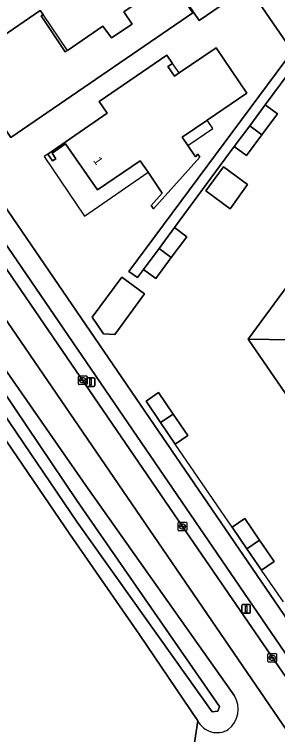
# Model space of a CAD drawing. Extents: x 155275 to 156265, y 382654 to 383635.
# Drawn here: x 155707.5 to 155738, y 383185 to 383268.4 of the extents above; entities that cross this region are included whole.
import ezdxf

# ---------------------------------------------------------------- set-up
doc = ezdxf.new("R2010")
doc.units = 0
for name, color, linetype in [('IMGEO_Erf', 7, 'Continuous'), ('IMGEO_Groenvoorziening', 7, 'Continuous'), ('IMGEO_Haag', 7, 'Continuous'), ('IMGEO_Hek', 7, 'Continuous'), ('IMGEO_Kolk', 7, 'Continuous'), ('IMGEO_Lichtmast', 7, 'Continuous'), ('IMGEO_Loofbos', 7, 'Continuous'), ('IMGEO_Oever', 7, 'Continuous'), ('IMGEO_Pand', 7, 'Continuous'), ('IMGEO_Pand_nummerreeks', 7, 'Continuous'), ('IMGEO_Pand_overbouw', 7, 'Continuous'), ('IMGEO_Rijbaan_lokaal_gesloten', 7, 'Continuous'), ('IMGEO_Voetpad_open', 7, 'Continuous'), ('IMGEO_Waterloop', 7, 'Continuous')]:
    doc.layers.add(name, color=color, linetype=linetype)

msp = doc.modelspace()

# ---------------------------------------------------------------- linework, layer by layer
at = {"layer": 'IMGEO_Erf'}
for points in [[(155693.884, 383330.96), (155734.469, 383271.59), (155728.87, 383267.725), (155692.93, 383320.467), (155688.369, 383327.082)], [(155685.56, 383327.69), (155661.788, 383311.41), (155661.818, 383311.37), (155722.08, 383223.219), (155746.422, 383187.612), (155746.888, 383186.944), (155747.971, 383187.224)], [(155745.485, 383270.128), (155742.752, 383266.412), (155744.176, 383265.359), (155742.385, 383262.935), (155740.594, 383260.512), (155739.169, 383261.565), (155736.524, 383257.973), (155737.942, 383256.92), (155736.147, 383254.502), (155734.353, 383252.085), (155732.935, 383253.137), (155726.011, 383243.752), (155727.435, 383242.698), (155725.643, 383240.277), (155723.851, 383237.856), (155722.428, 383238.91), (155721.741, 383237.982), (155720.716, 383238.675), (155753.838, 383283.279)], [(155739.704, 383223.29), (155734.527, 383230.848), (155740.14, 383238.453)]]:
    msp.add_lwpolyline(points, dxfattribs=at)
for points in [[(155734.583, 383271.594), (155742.867, 383277.178), (155744.174, 383279.002), (155741.521, 383282.885), (155742.428, 383283.521), (155739.813, 383287.344), (155749.57, 383293.989), (155754.229, 383287.144), (155752.824, 383286.188), (155752.675, 383286.086), (155752.585, 383286.218), (155751.334, 383285.368), (155751.99, 383284.392), (155753.037, 383282.834), (155739.444, 383264.478)], [(155728.147, 383268.629), (155707.057, 383254.188), (155704.717, 383257.623), (155705.227, 383257.972), (155704.294, 383259.337), (155704.145, 383259.236), (155701.658, 383262.871), (155710.458, 383268.888), (155710.791, 383268.434), (155710.55, 383268.256), (155713.354, 383264.091), (155713.617, 383264.267), (155717.71, 383267.089), (155718.705, 383265.728), (155721.105, 383267.326), (155720.14, 383268.738), (155725.534, 383272.422)], [(155734.407, 383259.334), (155729.803, 383256.198), (155729.751, 383256.162), (155726.905, 383254.223), (155727.564, 383253.254), (155728.445, 383251.962), (155728.711, 383252.244), (155728.949, 383251.893), (155723.566, 383245.941), (155723.308, 383246.322), (155724.598, 383247.753), (155722.951, 383250.17), (155722.046, 383251.498), (155717.08, 383248.118), (155713.404, 383253.462), (155711.832, 383252.387), (155712.272, 383251.719), (155711.884, 383251.464), (155711.333, 383252.262), (155718.216, 383257.009), (155717.282, 383258.364), (155725.125, 383263.723), (155725.785, 383262.769), (155725.246, 383262.397), (155726.007, 383261.296), (155726.548, 383261.665), (155730.828, 383264.587)], [(155734.487, 383248.749), (155732.466, 383245.916), (155729.635, 383248.005), (155731.701, 383250.805)], [(155722.555, 383236.09), (155719.101, 383231.389), (155717.78, 383231.439), (155716.477, 383233.378), (155719.909, 383238)], [(155727.572, 383219.678), (155726.107, 383218.678), (155724.41, 383221.165), (155722.713, 383223.652), (155724.178, 383224.652), (155725.875, 383222.165)], [(155737.567, 383205.079), (155736.107, 383204.078), (155734.403, 383206.563), (155732.698, 383209.047), (155734.158, 383210.049), (155735.862, 383207.564)]]:
    msp.add_lwpolyline(points, close=True, dxfattribs=at)
at = {"layer": 'IMGEO_Groenvoorziening'}
for points in [[(155724.288, 383171.628), (155724.536, 383171.272), (155727.184, 383173.115), (155741.62, 383181.726), (155659.414, 383301.908), (155653.216, 383310.97)], [(155661.264, 383305.321), (155662.23, 383303.795), (155718.824, 383220.994), (155726.923, 383209.144), (155742.91, 383185.882), (155743.508, 383186.026), (155744.463, 383186.256), (155720.116, 383221.876), (155661.229, 383308.029)], [(155652.603, 383306.481), (155666.3, 383286.64), (155695.288, 383243.3), (155715.747, 383213.896), (155732.948, 383189.534)], [(155728.723, 383186.646), (155727.137, 383176.194), (155722.162, 383175.473), (155711.113, 383178.69), (155713.945, 383176.906), (155717.284, 383175.138), (155722.257, 383173.065)]]:
    msp.add_lwpolyline(points, dxfattribs=at)
for centre, radius, start, end in [((155730.411, 383187.98), 2.975, 308.07903, 31.49251), ((155730.943, 383187.744), 2.477, 206.32515, 301.7411)]:
    msp.add_arc(centre, radius, start, end, dxfattribs=at)
at = {"layer": 'IMGEO_Haag'}
msp.add_lwpolyline([(155661.264, 383305.321), (155662.23, 383303.795), (155718.824, 383220.994), (155726.923, 383209.144), (155742.91, 383185.882), (155743.508, 383186.026), (155744.463, 383186.256), (155720.116, 383221.876), (155661.229, 383308.029)], dxfattribs=at)
at = {"layer": 'IMGEO_Hek'}
for points in [[(155732.698, 383209.047), (155726.107, 383218.678)], [(155738.647, 383200.418), (155736.107, 383204.078)]]:
    msp.add_lwpolyline(points, dxfattribs=at)
at = {"layer": 'IMGEO_Kolk'}
for p, q in [((155714.878, 383225.653), (155714.878, 383226.505)), ((155714.953, 383226.579), (155715.805, 383226.579)), ((155715.879, 383226.505), (155715.879, 383225.653)), ((155715.805, 383225.579), (155714.953, 383225.579)), ((155715.137, 383226.073), (155715.137, 383226.085)), ((155715.575, 383226.036), (155715.177, 383226.036)), ((155715.18, 383226.122), (155715.578, 383226.122)), ((155715.389, 383225.799), (155715.364, 383225.799)), ((155715.366, 383226.359), (155715.391, 383226.359)), ((155715.621, 383226.085), (155715.621, 383226.073)), ((155726.422, 383208.718), (155726.422, 383209.57)), ((155726.497, 383209.644), (155727.349, 383209.644)), ((155726.681, 383209.138), (155726.681, 383209.15)), ((155727.119, 383209.101), (155726.721, 383209.101)), ((155726.724, 383209.187), (155727.122, 383209.187)), ((155726.933, 383208.864), (155726.908, 383208.864)), ((155726.91, 383209.424), (155726.935, 383209.424)), ((155727.165, 383209.15), (155727.165, 383209.138)), ((155727.423, 383209.57), (155727.423, 383208.718)), ((155727.349, 383208.644), (155726.497, 383208.644)), ((155736.832, 383193.505), (155736.832, 383194.357)), ((155736.907, 383194.431), (155737.759, 383194.431)), ((155737.091, 383193.925), (155737.091, 383193.937)), ((155737.529, 383193.888), (155737.131, 383193.888)), ((155737.134, 383193.974), (155737.532, 383193.974)), ((155737.32, 383194.211), (155737.345, 383194.211)), ((155737.575, 383193.937), (155737.575, 383193.925)), ((155737.833, 383194.357), (155737.833, 383193.505)), ((155737.759, 383193.431), (155736.907, 383193.431)), ((155737.343, 383193.651), (155737.318, 383193.651))]:
    msp.add_line(p, q, dxfattribs=at)
for points in [[(155714.878, 383225.653), (155714.878, 383226.505)], [(155714.953, 383226.579), (155715.805, 383226.579)], [(155715.879, 383226.505), (155715.879, 383225.653)], [(155715.805, 383225.579), (155714.953, 383225.579)], [(155726.422, 383208.718), (155726.422, 383209.57)], [(155726.497, 383209.644), (155727.349, 383209.644)], [(155727.423, 383209.57), (155727.423, 383208.718)], [(155727.349, 383208.644), (155726.497, 383208.644)], [(155736.832, 383193.505), (155736.832, 383194.357)], [(155736.907, 383194.431), (155737.759, 383194.431)], [(155737.833, 383194.357), (155737.833, 383193.505)], [(155737.759, 383193.431), (155736.907, 383193.431)]]:
    msp.add_lwpolyline(points, dxfattribs=at)
for centre, radius, start, end in [((155714.955, 383226.503), 0.0765, 91.55205, 178.44795), ((155714.955, 383226.503), 0.0765, 91.55205, 178.44795), ((155715.803, 383226.503), 0.0765, 1.55205, 88.44795), ((155715.803, 383226.503), 0.0765, 1.55205, 88.44795), ((155714.955, 383225.655), 0.0765, 181.55205, 268.44795), ((155714.955, 383225.655), 0.0765, 181.55205, 268.44795), ((155715.177, 383226.082), 0.0403, 85.87752, 175.75265), ((155715.174, 383226.072), 0.0366, 178.93798, 274.71019), ((155715.578, 383226.079), 0.043, 264.86636, 352.45326), ((155715.582, 383226.084), 0.0386, 1.73085, 96.63898), ((155715.803, 383225.655), 0.0765, 271.55205, 358.44795), ((155715.803, 383225.655), 0.0765, 271.55205, 358.44795), ((155726.499, 383209.568), 0.0765, 91.55205, 178.44795), ((155726.499, 383209.568), 0.0765, 91.55205, 178.44795), ((155726.721, 383209.147), 0.0403, 85.87752, 175.75265), ((155726.718, 383209.137), 0.0366, 178.93798, 274.71019), ((155727.122, 383209.144), 0.043, 264.86636, 352.45326), ((155727.126, 383209.149), 0.0386, 1.73085, 96.63898), ((155727.347, 383209.568), 0.0765, 1.55205, 88.44795), ((155727.347, 383209.568), 0.0765, 1.55205, 88.44795), ((155726.499, 383208.72), 0.0765, 181.55205, 268.44795), ((155726.499, 383208.72), 0.0765, 181.55205, 268.44795), ((155727.347, 383208.72), 0.0765, 271.55205, 358.44795), ((155727.347, 383208.72), 0.0765, 271.55205, 358.44795), ((155736.909, 383194.355), 0.0765, 91.55205, 178.44795), ((155736.909, 383194.355), 0.0765, 91.55205, 178.44795), ((155737.131, 383193.934), 0.0403, 85.87752, 175.75265), ((155737.128, 383193.924), 0.0366, 178.93798, 274.71019), ((155737.532, 383193.931), 0.043, 264.86636, 352.45326), ((155737.536, 383193.936), 0.0386, 1.73085, 96.63898), ((155737.757, 383194.355), 0.0765, 1.55205, 88.44795), ((155737.757, 383194.355), 0.0765, 1.55205, 88.44795), ((155736.909, 383193.507), 0.0765, 181.55205, 268.44795), ((155736.909, 383193.507), 0.0765, 181.55205, 268.44795), ((155737.757, 383193.507), 0.0765, 271.55205, 358.44795), ((155737.757, 383193.507), 0.0765, 271.55205, 358.44795)]:
    msp.add_arc(centre, radius, start, end, dxfattribs=at)
for centre, major_axis, ratio, start_param, end_param in [((155715.365, 383226.079), (-0.387, 0.002), 0.722429, 4.712389, 7.853982), ((155715.39, 383226.079), (-0.39, 0.002), 0.717154, 1.570796, 4.712389), ((155726.909, 383209.144), (-0.387, 0.002), 0.722429, 4.712389, 7.853982), ((155726.934, 383209.144), (-0.39, 0.002), 0.717154, 1.570796, 4.712389), ((155737.319, 383193.931), (-0.387, 0.002), 0.722429, 4.712389, 7.853982), ((155737.344, 383193.931), (-0.39, 0.002), 0.717154, 1.570796, 4.712389)]:
    msp.add_ellipse(centre, major_axis=major_axis, ratio=ratio, start_param=start_param, end_param=end_param, dxfattribs=at)
at = {"layer": 'IMGEO_Lichtmast'}
for p, q in [((155715.784, 383225.465), (155715.784, 383226.265)), ((155715.784, 383226.265), (155715.784, 383225.465)), ((155715.884, 383226.365), (155716.674, 383226.365)), ((155716.674, 383226.365), (155715.884, 383226.365)), ((155716.774, 383226.265), (155716.774, 383225.465)), ((155716.774, 383225.465), (155716.774, 383226.265)), ((155716.674, 383225.365), (155715.884, 383225.365)), ((155715.884, 383225.365), (155716.674, 383225.365)), ((155733.805, 383199.193), (155733.805, 383199.993)), ((155733.805, 383199.993), (155733.805, 383199.193)), ((155733.905, 383200.093), (155734.695, 383200.093)), ((155734.695, 383200.093), (155733.905, 383200.093)), ((155734.795, 383199.993), (155734.795, 383199.193)), ((155734.795, 383199.193), (155734.795, 383199.993)), ((155734.695, 383199.093), (155733.905, 383199.093)), ((155733.905, 383199.093), (155734.695, 383199.093))]:
    msp.add_line(p, q, dxfattribs=at)
for points in [[(155716.204, 383226.24), (155716.354, 383226.24), (155716.354, 383225.49), (155716.204, 383225.49), (155716.204, 383226.24)], [(155734.225, 383199.968), (155734.375, 383199.968), (155734.375, 383199.218), (155734.225, 383199.218), (155734.225, 383199.968)]]:
    msp.add_lwpolyline(points, dxfattribs=at)
for centre, start, end in [((155715.884, 383226.265), 90, 180), ((155715.884, 383226.265), 90, 180), ((155716.674, 383226.265), 0, 90), ((155716.674, 383226.265), 360, 90), ((155715.884, 383225.465), 180, 270), ((155715.884, 383225.465), 180, 270), ((155716.674, 383225.465), 270, 0), ((155716.674, 383225.465), 270, 0), ((155733.905, 383199.993), 90, 180), ((155733.905, 383199.993), 90, 180), ((155734.695, 383199.993), 0, 90), ((155734.695, 383199.993), 360, 90), ((155733.905, 383199.193), 180, 270), ((155733.905, 383199.193), 180, 270), ((155734.695, 383199.193), 270, 0), ((155734.695, 383199.193), 270, 0)]:
    msp.add_arc(centre, 0.1, start, end, dxfattribs=at)
at = {"layer": 'IMGEO_Loofbos'}
msp.add_lwpolyline([(155710.048, 383179.361), (155711.113, 383178.69), (155722.162, 383175.473), (155727.137, 383176.194), (155728.723, 383186.646), (155722.016, 383196.56), (155713.872, 383208.237), (155684.729, 383250.992), (155668.129, 383275.492), (155648.012, 383304.606)], dxfattribs=at)
at = {"layer": 'IMGEO_Oever'}
msp.add_lwpolyline([(155731.242, 383188.308), (155731.02, 383187.751), (155730.364, 383187.664), (155714.72, 383209.654), (155670.177, 383275.322), (155648.619, 383307.02), (155649.298, 383307.441), (155676.91, 383268.261), (155714.708, 383212.148)], close=True, dxfattribs=at)
for points in [[(155732.948, 383189.534), (155715.747, 383213.896), (155695.288, 383243.3), (155666.3, 383286.64), (155652.603, 383306.481)], [(155648.012, 383304.606), (155668.129, 383275.492), (155684.729, 383250.992), (155713.872, 383208.237), (155722.016, 383196.56), (155728.723, 383186.646)]]:
    msp.add_lwpolyline(points, dxfattribs=at)
for centre, radius, start, end in [((155730.411, 383187.98), 2.975, 308.07903, 31.49251), ((155730.943, 383187.744), 2.477, 206.32515, 301.7411)]:
    msp.add_arc(centre, radius, start, end, dxfattribs=at)
at = {"layer": 'IMGEO_Pand'}
for points in [[(155753.037, 383282.834), (155751.99, 383284.392), (155751.334, 383285.368), (155752.585, 383286.218), (155752.675, 383286.086), (155752.824, 383286.188), (155754.229, 383287.144), (155749.57, 383293.989), (155739.813, 383287.344), (155742.428, 383283.521), (155741.521, 383282.885), (155744.174, 383279.002), (155742.867, 383277.178), (155734.583, 383271.594), (155739.444, 383264.478)], [(155704.717, 383257.623), (155707.057, 383254.188), (155728.147, 383268.629), (155725.534, 383272.422), (155720.14, 383268.738), (155721.105, 383267.326), (155718.705, 383265.728), (155717.71, 383267.089), (155713.617, 383264.267), (155713.354, 383264.091), (155710.55, 383268.256), (155710.791, 383268.434), (155710.458, 383268.888), (155701.658, 383262.871), (155704.145, 383259.236), (155704.294, 383259.337), (155705.227, 383257.972)], [(155729.751, 383256.162), (155729.803, 383256.198), (155734.407, 383259.334), (155730.828, 383264.587), (155726.548, 383261.665), (155726.007, 383261.296), (155725.246, 383262.397), (155725.785, 383262.769), (155725.125, 383263.723), (155717.282, 383258.364), (155718.216, 383257.009), (155711.333, 383252.262), (155711.884, 383251.464), (155712.272, 383251.719), (155711.832, 383252.387), (155713.404, 383253.462), (155717.08, 383248.118), (155722.046, 383251.498), (155722.951, 383250.17), (155724.598, 383247.753), (155723.308, 383246.322), (155723.566, 383245.941), (155728.949, 383251.893), (155728.711, 383252.244), (155728.445, 383251.962), (155727.564, 383253.254), (155726.905, 383254.223)], [(155736.147, 383254.502), (155737.942, 383256.92), (155736.524, 383257.973), (155734.73, 383255.555)], [(155736.147, 383254.502), (155734.73, 383255.555), (155732.935, 383253.137), (155734.353, 383252.085)], [(155734.487, 383248.749), (155731.701, 383250.805), (155729.635, 383248.005), (155732.466, 383245.916)], [(155724.219, 383241.331), (155725.643, 383240.277), (155727.435, 383242.698), (155726.011, 383243.752)], [(155724.219, 383241.331), (155722.428, 383238.91), (155723.851, 383237.856), (155725.643, 383240.277)], [(155744.353, 383230.665), (155746.421, 383233.476), (155747.22, 383232.892), (155747.379, 383233.106), (155740.14, 383238.453), (155734.527, 383230.848)], [(155719.909, 383238), (155716.477, 383233.378), (155717.78, 383231.439), (155719.101, 383231.389), (155722.555, 383236.09)], [(155744.353, 383230.665), (155734.527, 383230.848), (155739.704, 383223.29), (155739.81, 383223.136), (155742.576, 383225.143), (155746.415, 383227.66), (155746.309, 383227.814)], [(155724.41, 383221.165), (155725.875, 383222.165), (155724.178, 383224.652), (155722.713, 383223.652)], [(155724.41, 383221.165), (155726.107, 383218.678), (155727.572, 383219.678), (155725.875, 383222.165)], [(155734.403, 383206.563), (155735.862, 383207.564), (155734.158, 383210.049), (155732.698, 383209.047)], [(155734.403, 383206.563), (155736.107, 383204.078), (155737.567, 383205.079), (155735.862, 383207.564)]]:
    msp.add_lwpolyline(points, close=True, dxfattribs=at)
at = {"layer": 'IMGEO_Pand_overbouw'}
for points in [[(155713.617, 383264.267), (155710.791, 383268.434), (155710.55, 383268.256), (155713.354, 383264.091)], [(155726.548, 383261.665), (155725.785, 383262.769), (155725.246, 383262.397), (155726.007, 383261.296)], [(155730.461, 383255.237), (155729.803, 383256.198), (155729.751, 383256.162), (155726.905, 383254.223), (155727.564, 383253.254)], [(155711.333, 383252.262), (155710.907, 383251.968), (155715.606, 383245.069), (155722.951, 383250.17), (155722.046, 383251.498), (155717.08, 383248.118), (155713.404, 383253.462), (155711.832, 383252.387), (155712.272, 383251.719), (155711.884, 383251.464)]]:
    msp.add_lwpolyline(points, close=True, dxfattribs=at)
at = {"layer": 'IMGEO_Rijbaan_lokaal_gesloten'}
for points in [[(155662.23, 383303.795), (155659.414, 383301.908), (155741.62, 383181.726), (155742.144, 383180.959)], [(155743.419, 383185.124), (155742.91, 383185.882), (155726.923, 383209.144), (155718.824, 383220.994), (155662.23, 383303.795)]]:
    msp.add_lwpolyline(points, dxfattribs=at)
at = {"layer": 'IMGEO_Voetpad_open'}
for points in [[(155688.369, 383327.082), (155692.93, 383320.467), (155728.87, 383267.725), (155734.469, 383271.59), (155693.884, 383330.96)], [(155660.2, 383309.537), (155661.229, 383308.029), (155720.116, 383221.876), (155744.463, 383186.256), (155746.888, 383186.944), (155746.422, 383187.612), (155722.08, 383223.219), (155661.818, 383311.37)]]:
    msp.add_lwpolyline(points, dxfattribs=at)
msp.add_lwpolyline([(155740.96, 383263.989), (155742.752, 383266.412), (155745.485, 383270.128), (155747.276, 383272.548), (155749.067, 383274.967), (155754.741, 383282.576), (155757.038, 383285.669), (155758.243, 383286.581), (155757.279, 383288.068), (155757.257, 383288.039), (155756.383, 383286.856), (155756.341, 383286.918), (155756.272, 383286.834), (155753.838, 383283.279), (155720.716, 383238.675), (155721.741, 383237.982), (155722.428, 383238.91), (155724.219, 383241.331), (155726.011, 383243.752), (155732.935, 383253.137), (155734.73, 383255.555), (155736.524, 383257.973), (155739.169, 383261.565)], close=True, dxfattribs=at)
at = {"layer": 'IMGEO_Waterloop'}
msp.add_lwpolyline([(155648.619, 383307.02), (155670.177, 383275.322), (155714.72, 383209.654), (155730.364, 383187.664), (155731.02, 383187.751), (155731.242, 383188.308), (155714.708, 383212.148), (155676.91, 383268.261), (155649.298, 383307.441)], close=True, dxfattribs=at)

# ---------------------------------------------------------------- texts
at = {"layer": 'IMGEO_Pand_nummerreeks'}
msp.add_text('1', height=1, rotation=304.5205, dxfattribs=at).set_placement((155716.556, 383251.525))

doc.saveas('drawing.dxf')
